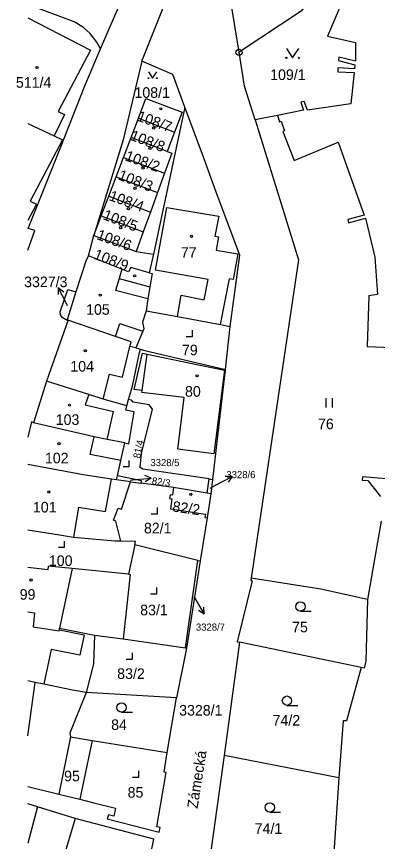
# Model space of a CAD drawing. Extents: x -600849 to -599899, y -1204328 to -1203436.
# Drawn here: x -600845 to -600787, y -1204028.8 to -1203896.5 of the extents above; entities that cross this region are included whole.
import ezdxf

# ---------------------------------------------------------------- set-up
doc = ezdxf.new("R2010")
doc.units = 0
for name, color, linetype in [('Vrstva 1', 7, 'Continuous'), ('Vrstva 2', 7, 'Continuous'), ('Vrstva 3', 7, 'Continuous'), ('Vrstva 4', 7, 'Continuous'), ('Vrstva 5', 7, 'Continuous'), ('Vrstva 7', 7, 'Continuous'), ('Vrstva 8', 7, 'Continuous')]:
    doc.layers.add(name, color=color, linetype=linetype)

msp = doc.modelspace()

# ---------------------------------------------------------------- linework, layer by layer
at = {"layer": 'Vrstva 1'}
for p, q in [((-600809.25, -1203902.22), (-600812.31, -1203883.27)), ((-600831.48, -1203901.67), (-600828.56, -1203894.86)), ((-600808.37, -1203907.68), (-600809.25, -1203902.22)), ((-600806.7, -1203913.03), (-600808.37, -1203907.68)), ((-600817.98, -1203911.02), (-600823.01, -1203934.6)), ((-600814.82, -1203919.45), (-600817.98, -1203911.02)), ((-600803.11, -1203912.34), (-600806.7, -1203913.03)), ((-600843.16, -1203913.63), (-600838.94, -1203915.63)), ((-600826.58, -1203915.9), (-600825.39, -1203912.81)), ((-600825.39, -1203912.81), (-600819.59, -1203915.01)), ((-600819.59, -1203915.01), (-600820.78, -1203918.13)), ((-600827.8, -1203919.1), (-600826.58, -1203915.9)), ((-600820.78, -1203918.13), (-600826.58, -1203915.9)), ((-600843.1, -1203930.47), (-600837.83, -1203917.4)), ((-600828.97, -1203922.17), (-600827.8, -1203919.1)), ((-600827.8, -1203919.1), (-600821.22, -1203921.63)), ((-600821.22, -1203921.63), (-600822.34, -1203924.72)), ((-600830.17, -1203925.31), (-600828.97, -1203922.17)), ((-600828.97, -1203922.17), (-600822.34, -1203924.72)), ((-600831.37, -1203928.45), (-600830.17, -1203925.31)), ((-600830.17, -1203925.31), (-600823.48, -1203927.88)), ((-600822.34, -1203924.72), (-600823.48, -1203927.88)), ((-600832.56, -1203931.58), (-600831.37, -1203928.45)), ((-600831.37, -1203928.45), (-600824.62, -1203931.03)), ((-600823.48, -1203927.88), (-600824.62, -1203931.03)), ((-600843.1, -1203930.47), (-600843.16, -1203930.44)), ((-600824.62, -1203931.03), (-600825.76, -1203934.18)), ((-600833.43, -1203934.85), (-600832.56, -1203931.58)), ((-600832.56, -1203931.58), (-600825.76, -1203934.18)), ((-600833.43, -1203934.85), (-600833.8, -1203935.57)), ((-600825.76, -1203934.18), (-600823.01, -1203934.6)), ((-600823.01, -1203934.6), (-600823.67, -1203937.59)), ((-600810.68, -1203946.18), (-600809.15, -1203934.78)), ((-600833.8, -1203935.57), (-600835.43, -1203940.66)), ((-600835.43, -1203940.66), (-600836.86, -1203945.15)), ((-600836.75, -1203945.3), (-600840.15, -1203954.95)), ((-600836.86, -1203945.15), (-600836.72, -1203945.2)), ((-600836.72, -1203945.2), (-600836.75, -1203945.3)), ((-600811.42, -1203953.08), (-600810.68, -1203946.18)), ((-600825.83, -1203949.64), (-600825.08, -1203949.84)), ((-600840.15, -1203954.95), (-600842.23, -1203961.63)), ((-600827.24, -1203958.92), (-600826.97, -1203957.91)), ((-600828.92, -1203970.79), (-600828.75, -1203970.15)), ((-600826.65, -1203971.09), (-600828.92, -1203970.79)), ((-600814.35, -1203972.93), (-600814.03, -1203970.65)), ((-600814.03, -1203970.65), (-600813.52, -1203970.72)), ((-600813.52, -1203970.72), (-600813.79, -1203973.03)), ((-600826.65, -1203971.09), (-600824.96, -1203971.31)), ((-600819.77, -1203972), (-600824.96, -1203971.31)), ((-600814.35, -1203972.93), (-600819.77, -1203972)), ((-600813.79, -1203973.03), (-600814.39, -1203976.89)), ((-600813.79, -1203973.03), (-600814.35, -1203972.93)), ((-600814.39, -1203976.89), (-600815.5, -1203983.8)), ((-600825.98, -1203981.21), (-600827.01, -1203985.91)), ((-600815.87, -1203983.71), (-600825.98, -1203981.21)), ((-600817.84, -1203997.74), (-600815.87, -1203983.71)), ((-600815.5, -1203983.8), (-600817.7, -1203997.76)), ((-600815.87, -1203983.71), (-600815.5, -1203983.8)), ((-600832.47, -1203995.67), (-600827.87, -1203996.3)), ((-600827.87, -1203996.3), (-600817.84, -1203997.74)), ((-600809.21, -1203996.83), (-600811.67, -1204014.98)), ((-600789.68, -1204000.89), (-600809.21, -1203996.83)), ((-600817.7, -1203997.76), (-600819.29, -1204005.72)), ((-600817.84, -1203997.74), (-600817.7, -1203997.76)), ((-600819.29, -1204005.72), (-600833.78, -1204004.89)), ((-600820.8, -1204014.49), (-600819.29, -1204005.72)), ((-600836.3, -1204012.02), (-600838.19, -1204021.17)), ((-600836.3, -1204012.02), (-600832.83, -1204012.58)), ((-600832.83, -1204012.58), (-600834.82, -1204022.01)), ((-600832.83, -1204012.58), (-600820.8, -1204014.49)), ((-600811.67, -1204014.98), (-600814.17, -1204032.93)), ((-600793.25, -1204018.6), (-600811.67, -1204014.98)), ((-600838.19, -1204021.17), (-600834.82, -1204022.01)), ((-600835.54, -1204025.11), (-600839.12, -1204037.04))]:
    msp.add_line(p, q, dxfattribs=at)
for points in [[(-600790.38, -1203882.29), (-600795.57, -1203890.93), (-600799.28, -1203895.63), (-600809.25, -1203902.22)], [(-600824.88, -1203903.67), (-600819.09, -1203889.18), (-600812.31, -1203883.27)], [(-600787.58, -1203883.54), (-600789.86, -1203888.84), (-600791.4, -1203888.21), (-600793.62, -1203893.51), (-600792.62, -1203893.88), (-600795.05, -1203899.63), (-600790.58, -1203900.68), (-600790.6, -1203903.65), (-600793.26, -1203903.01), (-600793.31, -1203903.54), (-600790.7, -1203904.24), (-600790.71, -1203904.87), (-600793.43, -1203904.71), (-600793.41, -1203905.37), (-600790.81, -1203905.49), (-600791.3, -1203910.49), (-600798.28, -1203911.49), (-600798.81, -1203910.12), (-600799.34, -1203910.23), (-600798.91, -1203911.53), (-600803.11, -1203912.34)], [(-600831.48, -1203901.67), (-600832.07, -1203900.59), (-600833.17, -1203899.21), (-600834.22, -1203898.26), (-600835.73, -1203897.33), (-600843.16, -1203894.56)], [(-600843.16, -1203896.68), (-600833.07, -1203901.9), (-600838.27, -1203911.7), (-600837.27, -1203912.2), (-600838.94, -1203915.63)], [(-600837.83, -1203917.4), (-600834.02, -1203907.61), (-600831.48, -1203901.67)], [(-600824.88, -1203903.67), (-600827.84, -1203916.26), (-600832.56, -1203931.58)], [(-600817.98, -1203911.02), (-600819.9, -1203905.79), (-600824.88, -1203903.67)], [(-600825.39, -1203912.81), (-600824.19, -1203909.66), (-600818.39, -1203911.84), (-600819.59, -1203915.01)], [(-600803.11, -1203912.34), (-600802.75, -1203913.37), (-600802.48, -1203913.28), (-600801.97, -1203914.82), (-600802.21, -1203914.94), (-600800.4, -1203919.59), (-600793.34, -1203916.66), (-600789.19, -1203928.35), (-600791.83, -1203929.06), (-600791.68, -1203929.59), (-600788.96, -1203928.81), (-600787.49, -1203935.07), (-600787.02, -1203941.08), (-600788.46, -1203941.28), (-600788.71, -1203949.38), (-600784.74, -1203949.55)], [(-600806.7, -1203913.03), (-600799.71, -1203935.52), (-600807.33, -1203986.54)], [(-600838.94, -1203915.63), (-600837.56, -1203916.28), (-600842.77, -1203926.11), (-600841.74, -1203926.59), (-600843.16, -1203929.2)], [(-600820.78, -1203918.13), (-600820.05, -1203918.41), (-600821.22, -1203921.63)], [(-600809.15, -1203934.78), (-600812.91, -1203924.64), (-600814.82, -1203919.45)], [(-600843.16, -1203933.96), (-600842.02, -1203930.82), (-600843.1, -1203930.47)], [(-600823.67, -1203937.59), (-600826.61, -1203936.75), (-600826.98, -1203937.41), (-600828.06, -1203936.98), (-600833.43, -1203934.85)], [(-600823.67, -1203937.59), (-600823.21, -1203937.72), (-600823.58, -1203939.82), (-600823.92, -1203941.77), (-600824.17, -1203943.67)], [(-600836.75, -1203945.3), (-600837.63, -1203944.74), (-600837.88, -1203944.33), (-600837.97, -1203943.84), (-600836.74, -1203940.24), (-600835.43, -1203940.66)], [(-600824.17, -1203943.67), (-600824.75, -1203945.52), (-600824.55, -1203946.57), (-600824.71, -1203946.94), (-600825.83, -1203949.64)], [(-600824.17, -1203943.67), (-600819.15, -1203944.61), (-600812.21, -1203945.9), (-600810.68, -1203946.18)], [(-600825.83, -1203949.64), (-600826.78, -1203949.38), (-600826.59, -1203948.64), (-600829.1, -1203947.79), (-600836.72, -1203945.2)], [(-600826.97, -1203957.91), (-600826.36, -1203955.75), (-600825.21, -1203950.38), (-600825.08, -1203949.84)], [(-600825.08, -1203949.84), (-600824.59, -1203949.97), (-600811.42, -1203953.08)], [(-600823.98, -1203950.66), (-600817.33, -1203952.05), (-600811.58, -1203953.18), (-600813.29, -1203966.62), (-600819.08, -1203965.88), (-600818.09, -1203957.59), (-600824.84, -1203956.76), (-600824.81, -1203956.46), (-600826.1, -1203956.3), (-600824.77, -1203950.47), (-600823.98, -1203950.66)], [(-600811.42, -1203953.08), (-600811.59, -1203954.08), (-600813.52, -1203970.72)], [(-600827.24, -1203958.92), (-600831.05, -1203957.83), (-600833.37, -1203957.1), (-600840.15, -1203954.95)], [(-600827.61, -1203964.88), (-600826.93, -1203965.02), (-600826.09, -1203959.88), (-600827.44, -1203959.61), (-600827.24, -1203958.92)], [(-600814.03, -1203970.65), (-600824.69, -1203969.09), (-600825.11, -1203968.79), (-600824.9, -1203966.58), (-600823.16, -1203959.47), (-600823.7, -1203958.78), (-600826.23, -1203958.34), (-600826.54, -1203958.02), (-600826.97, -1203957.91)], [(-600842.23, -1203961.63), (-600842.58, -1203961.51), (-600843.16, -1203963.93)], [(-600827.61, -1203964.88), (-600830.4, -1203964.31), (-600832.51, -1203963.89), (-600842.23, -1203961.63)], [(-600828.75, -1203970.15), (-600828.21, -1203967.66), (-600827.61, -1203964.88)], [(-600828.92, -1203970.79), (-600829.75, -1203970.66), (-600834.26, -1203969.97), (-600843.16, -1203968.31)], [(-600824.96, -1203971.31), (-600824.89, -1203970.93), (-600828.75, -1203970.15)], [(-600785, -1203970.69), (-600789.46, -1203970.33), (-600789.48, -1203970.84), (-600788.62, -1203970.92), (-600786.59, -1203973.45)], [(-600828.21, -1203980.63), (-600829.02, -1203977.41), (-600829.39, -1203977.27), (-600828.66, -1203975.32), (-600828.14, -1203975.51), (-600826.65, -1203971.09)], [(-600819.77, -1203972), (-600819.96, -1203973.24), (-600820.32, -1203973.19), (-600820.4, -1203973.77), (-600820.04, -1203973.82), (-600820.28, -1203975.42), (-600814.65, -1203976.3), (-600814.73, -1203976.84), (-600814.39, -1203976.89)], [(-600786.45, -1203977.4), (-600788.65, -1203989.96)], [(-600828.21, -1203980.63), (-600829.18, -1203980.62), (-600835.81, -1203980.05), (-600838.06, -1203979.67), (-600843.16, -1203978.84)], [(-600825.98, -1203981.21), (-600825.86, -1203980.67), (-600828.21, -1203980.63)], [(-600827.01, -1203985.91), (-600836.06, -1203985), (-600839.88, -1203984.61), (-600839.92, -1203985.21), (-600843.16, -1203984.87)], [(-600827.01, -1203985.91), (-600826.72, -1203985.95), (-600827.87, -1203996.3)], [(-600807.33, -1203986.54), (-600807.39, -1203986.94), (-600807.18, -1203986.97), (-600809.56, -1203996.76), (-600809.21, -1203996.83)], [(-600788.65, -1203989.96), (-600796.13, -1203988.31), (-600807.33, -1203986.54)], [(-600788.65, -1203989.96), (-600788.91, -1203999.85), (-600789.18, -1204000.99), (-600789.68, -1204000.89)], [(-600843.16, -1203991.94), (-600842.07, -1203992.09), (-600842.29, -1203994.34), (-600838.12, -1203994.99), (-600838.09, -1203994.83), (-600838.04, -1203994.55), (-600832.47, -1203995.67)], [(-600832.47, -1203995.67), (-600832.61, -1204000.3), (-600833.78, -1204004.89)], [(-600789.68, -1204000.89), (-600792.02, -1204009.42), (-600792.53, -1204009.44), (-600793.25, -1204018.6)], [(-600833.78, -1204004.89), (-600835.96, -1204004.51), (-600840.6, -1204003.55), (-600841.95, -1204003.27), (-600843.16, -1204003.02)], [(-600833.78, -1204004.89), (-600836.39, -1204011.4), (-600836.3, -1204012.02)], [(-600822.06, -1204027.28), (-600821.91, -1204026.54), (-600822.46, -1204026.41), (-600820.94, -1204017.7), (-600821.28, -1204017.67), (-600820.8, -1204014.49)], [(-600793.25, -1204018.6), (-600794.15, -1204032.23), (-600795.8, -1204031.86), (-600797.64, -1204037.95)], [(-600843.16, -1204019.94), (-600838.19, -1204021.17)], [(-600834.82, -1204022.01), (-600832.58, -1204022.56), (-600829.07, -1204023.43)], [(-600835.54, -1204025.11), (-600841.6, -1204023.22), (-600843.16, -1204022.74)], [(-600829.07, -1204023.43), (-600829.35, -1204024.72), (-600830.21, -1204024.51)], [(-600827.23, -1204046.67), (-600824.53, -1204036.21), (-600822.91, -1204028.4), (-600835.54, -1204025.11)], [(-600830.21, -1204024.51), (-600830.4, -1204025.17), (-600822.06, -1204027.28)]]:
    msp.add_lwpolyline(points, dxfattribs=at)
at = {"layer": 'Vrstva 3'}
for p, q in [((-600816.75, -1203947.8), (-600816.75, -1203946.8)), ((-600817.75, -1203947.8), (-600816.75, -1203947.8)), ((-600795.28, -1203959.19), (-600795.28, -1203957.69)), ((-600794.28, -1203959.19), (-600794.28, -1203957.69)), ((-600826.87, -1203968.66), (-600826.87, -1203967.66)), ((-600827.87, -1203968.66), (-600826.87, -1203968.66)), ((-600823.35, -1203976.24), (-600822.35, -1203976.24)), ((-600822.35, -1203976.24), (-600822.35, -1203975.24)), ((-600837.25, -1203981.6), (-600837.25, -1203980.6)), ((-600838.25, -1203981.6), (-600837.25, -1203981.6)), ((-600822.44, -1203989.07), (-600822.44, -1203988.07)), ((-600823.44, -1203989.07), (-600822.44, -1203989.07)), ((-600799.42, -1203991.87), (-600797.67, -1203991.87)), ((-600826.36, -1203999.55), (-600826.36, -1203998.55)), ((-600827.36, -1203999.55), (-600826.36, -1203999.55)), ((-600801.57, -1204006.95), (-600799.82, -1204006.95)), ((-600828.1, -1204008.06), (-600826.35, -1204008.06)), ((-600826.33, -1204018.45), (-600825.33, -1204018.45)), ((-600825.33, -1204018.45), (-600825.33, -1204017.45)), ((-600804.34, -1204024.07), (-600802.59, -1204024.07))]:
    msp.add_line(p, q, dxfattribs=at)
for points in [[(-600801.67, -1203901.61), (-600800.67, -1203903.11), (-600799.67, -1203901.61)], [(-600823.8, -1203905.37), (-600823.13, -1203906.38), (-600822.46, -1203905.37)]]:
    msp.add_lwpolyline(points, dxfattribs=at)
for centre, radius in [((-600801.67, -1203903.11), 0.1), ((-600799.67, -1203903.11), 0.1), ((-600823.8, -1203906.38), 0.067), ((-600822.46, -1203906.38), 0.067), ((-600799.42, -1203991.12), 0.75), ((-600828.1, -1204007.31), 0.75), ((-600801.57, -1204006.2), 0.75), ((-600804.34, -1204023.32), 0.75)]:
    msp.add_circle(centre, radius, dxfattribs=at)
at = {"layer": 'Vrstva 4'}
for p, q in [((-600822.68, -1203937.15), (-600820.82, -1203927.11)), ((-600820.82, -1203927.11), (-600812.52, -1203928.49)), ((-600812.52, -1203928.49), (-600813.13, -1203931.72)), ((-600813.13, -1203931.72), (-600812.56, -1203931.8)), ((-600812.56, -1203931.8), (-600812.91, -1203933.98)), ((-600812.91, -1203933.98), (-600809.43, -1203934.56)), ((-600809.43, -1203934.56), (-600810.21, -1203938.67)), ((-600828.06, -1203936.98), (-600828.5, -1203938.51)), ((-600814.2, -1203938.65), (-600822.68, -1203937.15)), ((-600828.5, -1203938.51), (-600829.06, -1203940.45)), ((-600828.5, -1203938.51), (-600823.58, -1203939.82)), ((-600814.83, -1203941.9), (-600814.2, -1203938.65)), ((-600812.21, -1203945.9), (-600810.81, -1203938.54)), ((-600810.21, -1203938.67), (-600810.81, -1203938.54)), ((-600823.92, -1203941.77), (-600829.06, -1203940.45)), ((-600819.15, -1203944.61), (-600818.53, -1203941.19)), ((-600818.53, -1203941.19), (-600814.83, -1203941.9)), ((-600829.1, -1203947.79), (-600828.4, -1203945.7)), ((-600828.4, -1203945.7), (-600824.71, -1203946.94)), ((-600827.97, -1203954.34), (-600826.78, -1203949.38)), ((-600824.81, -1203956.46), (-600823.98, -1203950.66)), ((-600831.05, -1203957.83), (-600830.02, -1203953.86)), ((-600830.02, -1203953.86), (-600827.97, -1203954.34)), ((-600833.37, -1203957.1), (-600833.93, -1203958.77)), ((-600833.93, -1203958.77), (-600829.38, -1203959.85)), ((-600830.4, -1203964.31), (-600829.38, -1203959.85)), ((-600833.13, -1203966.72), (-600832.51, -1203963.89)), ((-600828.21, -1203967.66), (-600833.13, -1203966.72)), ((-600830.7, -1203975.89), (-600829.75, -1203970.66)), ((-600835.02, -1203975.15), (-600835.81, -1203980.05)), ((-600835.02, -1203975.15), (-600830.7, -1203975.89)), ((-600836.06, -1203985), (-600838.04, -1203994.55)), ((-600838.09, -1203994.83), (-600834.13, -1203995.66)), ((-600834.13, -1203995.66), (-600834.8, -1203998.91)), ((-600839.42, -1203997.99), (-600840.6, -1204003.55)), ((-600834.8, -1203998.91), (-600839.42, -1203997.99)), ((-600843.16, -1204011.82), (-600841.95, -1204003.27)), ((-600841.6, -1204023.22), (-600843.16, -1204029.05))]:
    msp.add_line(p, q, dxfattribs=at)
at = {"layer": 'Vrstva 5'}
for centre in [(-600841.66, -1203904.67), (-600821.81, -1203911.3), (-600822.95, -1203914.37), (-600823.55, -1203917.63), (-600824.68, -1203920.79), (-600825.95, -1203924.04), (-600827.01, -1203927.29), (-600828.25, -1203930.35), (-600816.89, -1203931.74), (-600826.02, -1203938.07), (-600831.52, -1203941.18), (-600833.92, -1203950.09), (-600816.01, -1203954.11), (-600836.47, -1203958.82), (-600838.16, -1203964.98), (-600839.78, -1203972.75), (-600816.99, -1203973.12), (-600842.63, -1203986.84)]:
    msp.add_circle(centre, 0.175, dxfattribs=at)
at = {"layer": 'Vrstva 7'}
for p, q in [((-600836.91, -1203942.64), (-600838.27, -1203939.97)), ((-600838.27, -1203939.97), (-600837.37, -1203940.63)), ((-600838.27, -1203939.97), (-600838.26, -1203941.09)), ((-600836.8, -1203942.86), (-600836.91, -1203942.64)), ((-600826.74, -1203970.85), (-600826.34, -1203970.81)), ((-600826.34, -1203970.81), (-600823.35, -1203970.5)), ((-600823.35, -1203970.5), (-600824.4, -1203970.1)), ((-600823.35, -1203970.5), (-600824.3, -1203971.1)), ((-600813.03, -1203971.65), (-600810.38, -1203970.24)), ((-600810.38, -1203970.24), (-600811.5, -1203970.27)), ((-600810.38, -1203970.24), (-600811.03, -1203971.15)), ((-600813.9, -1203972.1), (-600813.03, -1203971.65)), ((-600816.51, -1203989.53), (-600816.38, -1203989.75)), ((-600816.38, -1203989.75), (-600814.83, -1203992.32)), ((-600814.83, -1203992.32), (-600815.78, -1203991.72)), ((-600814.83, -1203992.32), (-600814.92, -1203991.21))]:
    msp.add_line(p, q, dxfattribs=at)
at = {"layer": 'Vrstva 8'}
for radius in [0.5, 0.0303]:
    msp.add_circle((-600809.25, -1203902.22), radius, dxfattribs=at)

# ---------------------------------------------------------------- texts
at = {"layer": 'Vrstva 2'}
for s, height, p in [('511/4', 1.7, (-600845.06, -1203907.91)), ('109/1', 1.7, (-600804.27, -1203906.67)), ('108/1', 1.7, (-600826.04, -1203909.53)), ('77', 1.7, (-600818.6, -1203935.18)), ('3327/3', 1.7, (-600843.74, -1203939.89)), ('105', 1.7, (-600833.8, -1203944.32)), ('79', 1.7, (-600818.42, -1203950.82)), ('104', 1.7, (-600836.33, -1203953.43)), ('80', 1.7, (-600817.93, -1203957.46)), ('103', 1.7, (-600838.67, -1203961.98)), ('76', 1.7, (-600796.59, -1203962.67)), ('102', 1.7, (-600840.4, -1203968.14)), ('3328/5', 1.139, (-600823.48, -1203968.59)), ('3328/6', 1.14, (-600811.29, -1203970.52)), ('101', 1.7, (-600842.33, -1203976.02)), ('82/1', 1.7, (-600824.52, -1203979.38)), ('100', 1.7, (-600839.77, -1203984.6)), ('99', 1.7, (-600844.45, -1203990.01)), ('83/1', 1.7, (-600825.12, -1203992.51)), ('3328/7', 1.14, (-600816.18, -1203994.97)), ('75', 1.7, (-600800.75, -1203995.24)), ('83/2', 1.7, (-600828.81, -1204002.72)), ('3328/1', 1.7, (-600818.87, -1204008.59)), ('84', 1.7, (-600829.78, -1204010.9)), ('74/2', 1.7, (-600803.88, -1204010.2)), ('95', 1.7, (-600837.33, -1204019.13)), ('85', 1.7, (-600827.14, -1204021.75)), ('74/1', 1.7, (-600806.75, -1204027.56))]:
    msp.add_text(s, height=height, dxfattribs=at).set_placement(p)
for s, height, rotation, p in [('108/7', 1.7, 340, (-600825.76, -1203913.14)), ('108/8', 1.7, 339, (-600826.86, -1203916.22)), ('108/2', 1.7, 340, (-600827.69, -1203919.51)), ('108/3', 1.7, 339, (-600828.79, -1203922.58)), ('108/4', 1.7, 340, (-600830.25, -1203925.9)), ('108/5', 1.7, 339, (-600831.22, -1203928.96)), ('108/6', 1.7, 340, (-600832.23, -1203932.16)), ('108/9', 1.7, 339, (-600832.71, -1203935.29)), ('81/4', 1.14, 78, (-600825.15, -1203967.43)), ('82/3', 1.14, 352, (-600823.31, -1203971.48)), ('82/2', 1.7, 352, (-600820.03, -1203975.85))]:
    msp.add_text(s, height=height, rotation=rotation, dxfattribs=at).set_placement(p)
at = {"layer": 'Vrstva 7'}
msp.add_text('Zámecká', height=1.7, rotation=81, dxfattribs=at).set_placement((-600815.92, -1204023.58))

doc.saveas('drawing.dxf')
